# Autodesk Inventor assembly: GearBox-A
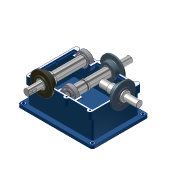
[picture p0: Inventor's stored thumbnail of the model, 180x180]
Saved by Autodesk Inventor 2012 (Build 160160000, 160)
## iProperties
+MSCProtocol1+ProtocolID: P00031106203922045
+MSCProtocol2+Protocol: P00031106203922045<@PID>[Version]<@EL>Version=2.2<@EL>[BaseView]<@EL>UpdateAll=0<@EL>[Main]<@EL>DataFile=SpiData|asmpart<@EL>View=MODEL<@EL>[View]<@EL>Data=(set
Created: 2003-11
Part Number: GearBox-A
Document SubType Name: Assembly
Manufacturer: Standard
Standards Organization: Custom
Description: GearBox.iam.
Control State: 0
Master: False
Checked Out: False
Shininess: 64.0
Length Units: 11269
Angle Units: 11279
Time Units: 11290
Mass Units: 11283
Length Display Precision: 3
Angle Display Precision: 2
Compacted: True
Density: 0.0
Volumn: 0.0
Area: 0.0
PropertySet Name: Model Information
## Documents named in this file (12)
- C:\CMU\Datasets\Session 5\Cluster Ex 1\Workspaces\Workspace\GearBox-A.iam
- C:\CMU\Datasets\Session 5\Cluster Ex 1\Workspaces\Workspace\Parts\CoverInput.ipt
- C:\CMU\Datasets\Session 5\Cluster Ex 1\Workspaces\Workspace\Parts\CoverOutput.ipt
- C:\CMU\Datasets\Session 5\Cluster Ex 1\Workspaces\Workspace\Parts\GearBoxBottom.ipt
- C:\CMU\Datasets\Session 5\Cluster Ex 1\Workspaces\Workspace\Parts\BaldorMotorLean.ipt
- C:\CMU\Datasets\Session 5\Cluster Ex 1\Workspaces\Workspace\GearBox-A\Design Accelerator\Shaft1.iam
- C:\CMU\Datasets\Session 5\Cluster Ex 1\Workspaces\Workspace\GearBox-A\Design Accelerator\Shaft2.iam
- C:\CMU\Datasets\Session 5\Cluster Ex 1\Workspaces\Workspace\GearBox-A\Design Accelerator\Bearing1.iam
- C:\CMU\Datasets\Session 5\Cluster Ex 1\Workspaces\Workspace\GearBox-A\Design Accelerator\Bearing2.iam
- C:\CMU\Datasets\Session 5\Cluster Ex 1\Workspaces\Workspace\GearBox-A\Design Accelerator\Bearing3.iam
- C:\CMU\Datasets\Session 5\Cluster Ex 1\Workspaces\Workspace\GearBox-A\Design Accelerator\Shaft4.iam
- C:\CMU\Datasets\Session 5\Cluster Ex 1\Workspaces\Workspace\GearBox-A\Design Accelerator\Bearing4.iam
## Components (11 placed, 5 different names)
1. GearBoxBottom:1 — Mate:4, Mate:5, Mate:6, Mate:7, Flush:1, Flush:2, Insert:1
2. CoverInput:1 — Mate:4, Mate:5, Mate:11, Mate:15
3. CoverOutput:1 — Mate:6, Mate:7, Mate:9
4. Shaft:1 [sub-assembly] — Mate:9, Flush:2, Mate:13, Flush:4
5. Shaft:2 [sub-assembly] — Mate:11, Flush:1, Mate:12, Flush:3, Mate:14
6. Bearing:1 [sub-assembly] — Mate:12, Flush:3
7. Bearing:2 [sub-assembly] — Mate:13, Flush:4
8. Bearing:3 [sub-assembly] — Mate:14, Mate:15
9. CoverInput:2 — Insert:1, Mate:16, Mate:17, Mate:18, Mate:19
10. Shaft:4 [sub-assembly] — Mate:16, Mate:19
11. Bearing:4 [sub-assembly] — Mate:17, Mate:18
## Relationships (19: Mate 14, Flush 4, Insert 1)
- Mate:4: GearBoxBottom:1 ↔ CoverInput:1
- Mate:5: GearBoxBottom:1 ↔ CoverInput:1
- Mate:6: GearBoxBottom:1 ↔ CoverOutput:1
- Mate:7: GearBoxBottom:1 ↔ CoverOutput:1
- Mate:9: CoverOutput:1 ↔ Shaft:1
- Mate:11: CoverInput:1 ↔ Shaft:2
- Flush:1: GearBoxBottom:1 ↔ Shaft:2
- Flush:2: GearBoxBottom:1 ↔ Shaft:1
- Mate:12: Shaft:2 ↔ Bearing:1
- Flush:3: Shaft:2 ↔ Bearing:1
- Mate:13: Shaft:1 ↔ Bearing:2
- Flush:4: Shaft:1 ↔ Bearing:2
- Mate:14: Shaft:2 ↔ Bearing:3
- Mate:15: CoverInput:1 ↔ Bearing:3
- Insert:1: GearBoxBottom:1 ↔ CoverInput:2
- Mate:16: CoverInput:2 ↔ Shaft:4
- Mate:17: CoverInput:2 ↔ Bearing:4
- Mate:18: CoverInput:2 ↔ Bearing:4
- Mate:19: CoverInput:2 ↔ Shaft:4
